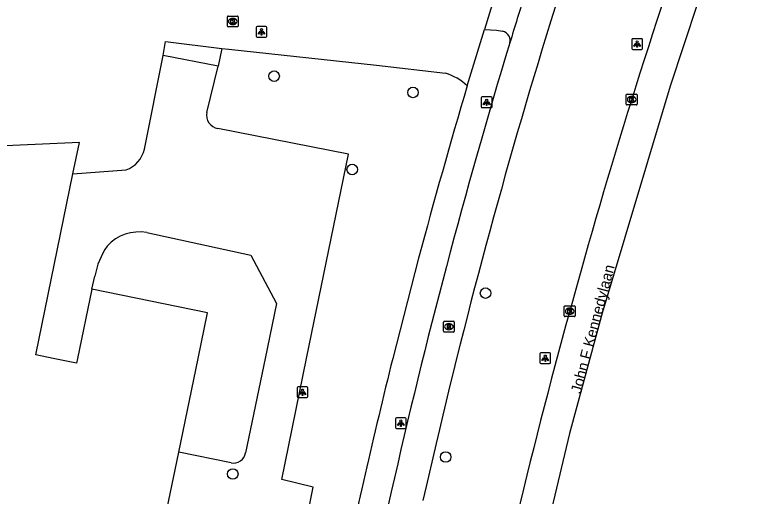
# Model space of a CAD drawing. Extents: x 161243 to 161752, y 384138 to 384885.
# Drawn here: x 161438.2 to 161506.3, y 384237.2 to 384281.9 of the extents above; entities that cross this region are included whole.
import ezdxf

# ---------------------------------------------------------------- set-up
doc = ezdxf.new("R2010")
doc.units = 0
for name, color, linetype in [('IMGEO_Boom', 7, 'Continuous'), ('IMGEO_Fietspad_gesloten', 7, 'Continuous'), ('IMGEO_Groenvoorziening', 7, 'Continuous'), ('IMGEO_Kolk', 7, 'Continuous'), ('IMGEO_Lichtpunt', 7, 'Continuous'), ('IMGEO_Openbare_ruimte_label', 7, 'Continuous'), ('IMGEO_Pand', 7, 'Continuous'), ('IMGEO_Rijbaan_lokaal_gesloten', 7, 'Continuous'), ('IMGEO_Rijbaan_lokaal_open', 7, 'Continuous'), ('IMGEO_Rioolput', 7, 'Continuous'), ('IMGEO_Voetpad_open', 7, 'Continuous')]:
    doc.layers.add(name, color=color, linetype=linetype)

msp = doc.modelspace()

# ---------------------------------------------------------------- linework, layer by layer
at = {"layer": 'IMGEO_Boom'}
for centre in [(161462.249, 384276.166), (161475.127, 384274.655), (161469.493, 384267.513), (161481.864, 384256.054), (161478.156, 384240.853), (161458.419, 384239.283)]:
    msp.add_circle(centre, 0.489, dxfattribs=at)
at = {"layer": 'IMGEO_Fietspad_gesloten'}
for centre, radius, start, end in [((162039.774, 384110.274), 577.749, 158.754785, 167.348346), ((162085.069, 384096.396), 628.16, 162.645157, 163.07631), ((162043.469, 384109.252), 584.62, 163.094928, 167.316644), ((162230.462, 384065.754), 776.602, 167.214855, 171.164573)]:
    msp.add_arc(centre, radius, start, end, dxfattribs=at)
at = {"layer": 'IMGEO_Groenvoorziening'}
msp.add_lwpolyline([(161457.397, 384278.741), (161458.047, 384278.662), (161471.733, 384277.186), (161478.143, 384276.429)], dxfattribs=at)
msp.add_arc((161476.684, 384271.558), 5.085, 46.92156, 73.32555, dxfattribs=at)
at = {"layer": 'IMGEO_Kolk'}
for p, q in [((161457.92, 384280.81), (161457.92, 384281.662)), ((161457.995, 384281.736), (161458.847, 384281.736)), ((161458.408, 384281.516), (161458.433, 384281.516)), ((161458.921, 384281.662), (161458.921, 384280.81)), ((161458.847, 384280.736), (161457.995, 384280.736)), ((161458.431, 384280.956), (161458.406, 384280.956)), ((161494.91, 384273.573), (161494.91, 384274.425)), ((161494.985, 384274.499), (161495.837, 384274.499)), ((161495.398, 384274.279), (161495.423, 384274.279)), ((161495.911, 384274.425), (161495.911, 384273.573)), ((161495.421, 384273.719), (161495.396, 384273.719)), ((161495.837, 384273.499), (161494.985, 384273.499)), ((161489.164, 384253.944), (161489.164, 384254.796)), ((161489.239, 384254.87), (161490.091, 384254.87)), ((161489.652, 384254.65), (161489.677, 384254.65)), ((161490.165, 384254.796), (161490.165, 384253.944)), ((161490.091, 384253.87), (161489.239, 384253.87)), ((161489.675, 384254.09), (161489.65, 384254.09))]:
    msp.add_line(p, q, dxfattribs=at)
for points in [[(161457.92, 384280.81), (161457.92, 384281.662)], [(161457.995, 384281.736), (161458.847, 384281.736)], [(161458.241, 384281.436), (161458.364, 384281.436), (161458.364, 384281.285), (161458.494, 384281.436), (161458.658, 384281.436), (161458.512, 384281.285), (161458.665, 384281.036), (161458.513, 384281.036), (161458.428, 384281.2), (161458.364, 384281.133), (161458.364, 384281.036), (161458.241, 384281.036), (161458.241, 384281.436)], [(161458.921, 384281.662), (161458.921, 384280.81)], [(161458.847, 384280.736), (161457.995, 384280.736)], [(161494.91, 384273.573), (161494.91, 384274.425)], [(161494.985, 384274.499), (161495.837, 384274.499)], [(161495.911, 384274.425), (161495.911, 384273.573)], [(161495.231, 384274.199), (161495.354, 384274.199), (161495.354, 384274.048), (161495.484, 384274.199), (161495.648, 384274.199), (161495.502, 384274.048), (161495.655, 384273.799), (161495.503, 384273.799), (161495.418, 384273.963), (161495.354, 384273.896), (161495.354, 384273.799), (161495.231, 384273.799), (161495.231, 384274.199)], [(161495.837, 384273.499), (161494.985, 384273.499)], [(161489.164, 384253.944), (161489.164, 384254.796)], [(161489.239, 384254.87), (161490.091, 384254.87)], [(161489.485, 384254.57), (161489.608, 384254.57), (161489.608, 384254.419), (161489.738, 384254.57), (161489.902, 384254.57), (161489.756, 384254.419), (161489.909, 384254.17), (161489.757, 384254.17), (161489.672, 384254.334), (161489.608, 384254.267), (161489.608, 384254.17), (161489.485, 384254.17), (161489.485, 384254.57)], [(161490.165, 384254.796), (161490.165, 384253.944)], [(161490.091, 384253.87), (161489.239, 384253.87)]]:
    msp.add_lwpolyline(points, dxfattribs=at)
for centre, start, end in [((161457.997, 384281.66), 91.55205, 178.44795), ((161457.997, 384281.66), 91.55205, 178.44795), ((161458.845, 384281.66), 1.55205, 88.44795), ((161458.845, 384281.66), 1.55205, 88.44795), ((161457.997, 384280.812), 181.55205, 268.44795), ((161457.997, 384280.812), 181.55205, 268.44795), ((161458.845, 384280.812), 271.55205, 358.44795), ((161458.845, 384280.812), 271.55205, 358.44795), ((161494.987, 384274.423), 91.55205, 178.44795), ((161494.987, 384274.423), 91.55205, 178.44795), ((161495.835, 384274.423), 1.55205, 88.44795), ((161495.835, 384274.423), 1.55205, 88.44795), ((161494.987, 384273.575), 181.55205, 268.44795), ((161494.987, 384273.575), 181.55205, 268.44795), ((161495.835, 384273.575), 271.55205, 358.44795), ((161495.835, 384273.575), 271.55205, 358.44795), ((161489.241, 384254.794), 91.55205, 178.44795), ((161489.241, 384254.794), 91.55205, 178.44795), ((161490.089, 384254.794), 1.55205, 88.44795), ((161490.089, 384254.794), 1.55205, 88.44795), ((161489.241, 384253.946), 181.55205, 268.44795), ((161489.241, 384253.946), 181.55205, 268.44795), ((161490.089, 384253.946), 271.55205, 358.44795), ((161490.089, 384253.946), 271.55205, 358.44795)]:
    msp.add_arc(centre, 0.0765, start, end, dxfattribs=at)
for centre, major_axis, ratio, start_param, end_param in [((161458.407, 384281.236), (-0.387, 0.002), 0.722429, 4.712389, 7.853982), ((161458.432, 384281.236), (-0.39, 0.002), 0.717154, 1.570796, 4.712389), ((161495.397, 384273.999), (-0.387, 0.002), 0.722429, 4.712389, 7.853982), ((161495.422, 384273.999), (-0.39, 0.002), 0.717154, 1.570796, 4.712389), ((161489.651, 384254.37), (-0.387, 0.002), 0.722429, 4.712389, 7.853982), ((161489.676, 384254.37), (-0.39, 0.002), 0.717154, 1.570796, 4.712389)]:
    msp.add_ellipse(centre, major_axis=major_axis, ratio=ratio, start_param=start_param, end_param=end_param, dxfattribs=at)
at = {"layer": 'IMGEO_Lichtpunt'}
for p, q in [((161460.583, 384280.685), (161460.583, 384279.878)), ((161460.583, 384280.685), (161460.583, 384279.878)), ((161461.485, 384280.78), (161460.677, 384280.78)), ((161461.485, 384280.78), (161460.677, 384280.78)), ((161461.579, 384279.878), (161461.579, 384280.685)), ((161461.579, 384279.878), (161461.579, 384280.685)), ((161460.677, 384279.784), (161461.485, 384279.784)), ((161460.677, 384279.784), (161461.485, 384279.784)), ((161495.414, 384279.545), (161495.414, 384278.738)), ((161495.414, 384279.545), (161495.414, 384278.738)), ((161496.316, 384279.64), (161495.508, 384279.64)), ((161496.316, 384279.64), (161495.508, 384279.64)), ((161496.41, 384278.738), (161496.41, 384279.545)), ((161496.41, 384278.738), (161496.41, 384279.545)), ((161495.508, 384278.644), (161496.316, 384278.644)), ((161495.508, 384278.644), (161496.316, 384278.644)), ((161481.464, 384274.145), (161481.464, 384273.338)), ((161481.464, 384274.145), (161481.464, 384273.338)), ((161482.366, 384274.24), (161481.558, 384274.24)), ((161482.366, 384274.24), (161481.558, 384274.24)), ((161482.46, 384273.338), (161482.46, 384274.145)), ((161482.46, 384273.338), (161482.46, 384274.145)), ((161481.558, 384273.244), (161482.366, 384273.244)), ((161481.558, 384273.244), (161482.366, 384273.244)), ((161486.901, 384250.415), (161486.901, 384249.608)), ((161486.901, 384250.415), (161486.901, 384249.608)), ((161487.803, 384250.51), (161486.995, 384250.51)), ((161487.803, 384250.51), (161486.995, 384250.51)), ((161487.897, 384249.608), (161487.897, 384250.415)), ((161487.897, 384249.608), (161487.897, 384250.415)), ((161486.995, 384249.514), (161487.803, 384249.514)), ((161486.995, 384249.514), (161487.803, 384249.514)), ((161464.383, 384247.263), (161464.383, 384246.456)), ((161464.383, 384247.263), (161464.383, 384246.456)), ((161465.285, 384247.358), (161464.477, 384247.358)), ((161465.285, 384247.358), (161464.477, 384247.358)), ((161465.379, 384246.456), (161465.379, 384247.263)), ((161465.379, 384246.456), (161465.379, 384247.263)), ((161464.477, 384246.362), (161465.285, 384246.362)), ((161464.477, 384246.362), (161465.285, 384246.362)), ((161473.5, 384244.399), (161473.5, 384243.592)), ((161473.5, 384244.399), (161473.5, 384243.592)), ((161474.402, 384244.494), (161473.594, 384244.494)), ((161474.402, 384244.494), (161473.594, 384244.494)), ((161474.496, 384243.592), (161474.496, 384244.399)), ((161474.496, 384243.592), (161474.496, 384244.399)), ((161473.594, 384243.498), (161474.402, 384243.498)), ((161473.594, 384243.498), (161474.402, 384243.498))]:
    msp.add_line(p, q, dxfattribs=at)
for points in [[(161460.957, 384280.349), (161460.996, 384280.321), (161460.808, 384280.059), (161460.77, 384280.086), (161460.957, 384280.349)], [(161461.059, 384280.301), (161461.106, 384280.301), (161461.106, 384279.979), (161461.059, 384279.979), (161461.059, 384280.301)], [(161461.169, 384280.321), (161461.207, 384280.348), (161461.394, 384280.086), (161461.355, 384280.058), (161461.169, 384280.321)], [(161495.788, 384279.209), (161495.827, 384279.181), (161495.639, 384278.919), (161495.601, 384278.946), (161495.788, 384279.209)], [(161495.89, 384279.161), (161495.937, 384279.161), (161495.937, 384278.839), (161495.89, 384278.839), (161495.89, 384279.161)], [(161496, 384279.181), (161496.038, 384279.208), (161496.225, 384278.946), (161496.186, 384278.918), (161496, 384279.181)], [(161481.838, 384273.809), (161481.877, 384273.781), (161481.689, 384273.519), (161481.651, 384273.546), (161481.838, 384273.809)], [(161481.94, 384273.761), (161481.987, 384273.761), (161481.987, 384273.439), (161481.94, 384273.439), (161481.94, 384273.761)], [(161482.05, 384273.781), (161482.088, 384273.808), (161482.275, 384273.546), (161482.236, 384273.518), (161482.05, 384273.781)], [(161487.275, 384250.079), (161487.314, 384250.051), (161487.126, 384249.789), (161487.088, 384249.816), (161487.275, 384250.079)], [(161487.377, 384250.031), (161487.424, 384250.031), (161487.424, 384249.709), (161487.377, 384249.709), (161487.377, 384250.031)], [(161487.487, 384250.051), (161487.525, 384250.078), (161487.712, 384249.816), (161487.673, 384249.788), (161487.487, 384250.051)], [(161464.757, 384246.927), (161464.796, 384246.899), (161464.608, 384246.637), (161464.57, 384246.664), (161464.757, 384246.927)], [(161464.859, 384246.879), (161464.906, 384246.879), (161464.906, 384246.557), (161464.859, 384246.557), (161464.859, 384246.879)], [(161464.969, 384246.899), (161465.007, 384246.926), (161465.194, 384246.664), (161465.155, 384246.636), (161464.969, 384246.899)], [(161473.874, 384244.063), (161473.913, 384244.035), (161473.725, 384243.773), (161473.687, 384243.8), (161473.874, 384244.063)], [(161473.976, 384244.015), (161474.023, 384244.015), (161474.023, 384243.693), (161473.976, 384243.693), (161473.976, 384244.015)], [(161474.086, 384244.035), (161474.124, 384244.062), (161474.311, 384243.8), (161474.272, 384243.772), (161474.086, 384244.035)]]:
    msp.add_lwpolyline(points, dxfattribs=at)
for centre in [(161461.082, 384280.483), (161495.913, 384279.343), (161481.963, 384273.943), (161487.4, 384250.213), (161464.882, 384247.061), (161473.999, 384244.197)]:
    msp.add_circle(centre, 0.0994, dxfattribs=at)
for centre, start, end in [((161460.677, 384280.685), 90, 180), ((161460.677, 384280.685), 90, 180), ((161461.485, 384280.685), 0, 90), ((161461.485, 384280.685), 0, 90), ((161460.677, 384279.878), 180, 270), ((161460.677, 384279.878), 180, 270), ((161461.485, 384279.878), 270, 0), ((161461.485, 384279.878), 270, 360), ((161495.508, 384279.545), 90, 180), ((161495.508, 384279.545), 90, 180), ((161496.316, 384279.545), 0, 90), ((161496.316, 384279.545), 0, 90), ((161495.508, 384278.738), 180, 270), ((161495.508, 384278.738), 180, 270), ((161496.316, 384278.738), 270, 0), ((161496.316, 384278.738), 270, 360), ((161481.558, 384274.145), 90, 180), ((161481.558, 384274.145), 90, 180), ((161482.366, 384274.145), 0, 90), ((161482.366, 384274.145), 0, 90), ((161481.558, 384273.338), 180, 270), ((161481.558, 384273.338), 180, 270), ((161482.366, 384273.338), 270, 0), ((161482.366, 384273.338), 270, 360), ((161486.995, 384250.415), 90, 180), ((161486.995, 384250.415), 90, 180), ((161487.803, 384250.415), 0, 90), ((161487.803, 384250.415), 0, 90), ((161486.995, 384249.608), 180, 270), ((161486.995, 384249.608), 180, 270), ((161487.803, 384249.608), 270, 0), ((161487.803, 384249.608), 270, 360), ((161464.477, 384247.263), 90, 180), ((161464.477, 384247.263), 90, 180), ((161465.285, 384247.263), 0, 90), ((161465.285, 384247.263), 0, 90), ((161464.477, 384246.456), 180, 270), ((161464.477, 384246.456), 180, 270), ((161465.285, 384246.456), 270, 0), ((161465.285, 384246.456), 270, 360), ((161473.594, 384244.399), 90, 180), ((161473.594, 384244.399), 90, 180), ((161474.402, 384244.399), 0, 90), ((161474.402, 384244.399), 0, 90), ((161473.594, 384243.592), 180, 270), ((161473.594, 384243.592), 180, 270), ((161474.402, 384243.592), 270, 0), ((161474.402, 384243.592), 270, 360)]:
    msp.add_arc(centre, 0.0946, start, end, dxfattribs=at)
at = {"layer": 'IMGEO_Pand'}
for points in [[(161443.595, 384267.101), (161444.19, 384270.006), (161409.789, 384268.472)], [(161445.345, 384256.428), (161444.012, 384250), (161443.92, 384249.556), (161441.755, 384250), (161440.16, 384250.327), (161443.595, 384267.101)], [(161453.42, 384241.315), (161455.21, 384250), (161456.081, 384254.229), (161445.345, 384256.428)], [(161452.162, 384235.232), (161453.42, 384241.315)]]:
    msp.add_lwpolyline(points, dxfattribs=at)
at = {"layer": 'IMGEO_Rijbaan_lokaal_gesloten'}
msp.add_lwpolyline([(161638.668, 384567.921), (161627.681, 384546.777), (161605.302, 384502.824), (161593.763, 384479.586), (161574.873, 384442.021), (161545.035, 384383.956), (161539.238, 384372.041), (161525.285, 384343.063), (161517.236, 384325.784), (161510.904, 384308.827), (161504.035, 384290.582), (161498.991, 384275.235), (161492.66, 384254.201), (161489.655, 384243.039), (161484.933, 384223.293), (161481.713, 384206.981), (161478.494, 384189.488), (161475.768, 384168.523)], dxfattribs=at)
for centre, radius, start, end in [((162042.579, 384103.171), 573.215, 160.615638, 164.705887), ((162060.147, 384097.056), 591.775, 164.583524, 168.642877)]:
    msp.add_arc(centre, radius, start, end, dxfattribs=at)
at = {"layer": 'IMGEO_Rijbaan_lokaal_open'}
for points in [[(161451.978, 384278.094), (161452.194, 384279.379), (161457.397, 384278.741)], [(161457.397, 384278.741), (161457.055, 384277.085)], [(161450.22, 384269.4), (161451.978, 384278.094)], [(161457.055, 384277.085), (161451.978, 384278.094)], [(161456.002, 384272.782), (161457.055, 384277.085)], [(161464.156, 384229.33), (161465.863, 384238.046), (161462.953, 384238.76), (161465.264, 384250), (161469.159, 384268.947), (161457.031, 384271.325)], [(161443.595, 384267.101), (161448.521, 384267.466)], [(161450.444, 384261.666), (161460.096, 384259.576), (161462.459, 384255.089), (161461.408, 384250), (161459.6, 384241.243)], [(161445.345, 384256.428), (161445.632, 384257.63)], [(161458.265, 384240.323), (161453.42, 384241.315)]]:
    msp.add_lwpolyline(points, dxfattribs=at)
for centre, radius, start, end in [((161457.21, 384272.543), 1.231, 168.80897, 261.654), ((161447.603, 384269.985), 2.681, 290.01163, 347.39039), ((161449.752, 384257.693), 4.033, 80.12473, 137.60477), ((161452.571, 384256.407), 7.046, 145.36033, 170.00376), ((161458.499, 384241.412), 1.114, 257.89373, 351.25072)]:
    msp.add_arc(centre, radius, start, end, dxfattribs=at)
at = {"layer": 'IMGEO_Rioolput'}
for p, q in [((161477.957, 384252.514), (161477.957, 384253.366)), ((161478.032, 384253.44), (161478.884, 384253.44)), ((161478.445, 384253.22), (161478.47, 384253.22)), ((161478.958, 384253.366), (161478.958, 384252.514)), ((161478.468, 384252.66), (161478.443, 384252.66)), ((161478.884, 384252.44), (161478.032, 384252.44))]:
    msp.add_line(p, q, dxfattribs=at)
for points in [[(161477.957, 384252.514), (161477.957, 384253.366)], [(161478.032, 384253.44), (161478.884, 384253.44)], [(161478.546, 384253.138), (161478.294, 384253.14), (161478.294, 384252.74)], [(161478.958, 384253.366), (161478.958, 384252.514)], [(161478.294, 384252.74), (161478.418, 384252.74), (161478.418, 384252.902), (161478.429, 384252.902)], [(161478.472, 384253.059), (161478.418, 384253.059), (161478.418, 384252.978)], [(161478.418, 384252.978), (161478.47, 384252.978)], [(161478.476, 384252.873), (161478.547, 384252.74), (161478.687, 384252.74), (161478.622, 384252.866)], [(161478.884, 384252.44), (161478.032, 384252.44)]]:
    msp.add_lwpolyline(points, dxfattribs=at)
for centre, radius, start, end in [((161478.034, 384253.364), 0.0765, 91.55205, 178.44795), ((161478.034, 384253.364), 0.0765, 91.55205, 178.44795), ((161478.545, 384253.028), 0.109, 350.36119, 89.41601), ((161478.882, 384253.364), 0.0765, 1.55205, 88.44795), ((161478.882, 384253.364), 0.0765, 1.55205, 88.44795), ((161478.034, 384252.516), 0.0765, 181.55205, 268.44795), ((161478.034, 384252.516), 0.0765, 181.55205, 268.44795), ((161478.428, 384252.849), 0.0533, 26.02933, 88.69889), ((161478.454, 384253.167), 0.19, 274.7715, 282.96867), ((161478.478, 384252.963), 0.0964, 77.00612, 93.18647), ((161478.492, 384253.02), 0.0378, 276.66336, 79.67722), ((161478.543, 384253.028), 0.112, 277.58423, 350.98172), ((161478.527, 384252.813), 0.108, 29.51342, 73.79051), ((161478.882, 384252.516), 0.0765, 271.55205, 358.44795), ((161478.882, 384252.516), 0.0765, 271.55205, 358.44795)]:
    msp.add_arc(centre, radius, start, end, dxfattribs=at)
for centre, major_axis, ratio, start_param, end_param in [((161478.444, 384252.94), (-0.387, 0.002), 0.722429, 4.712389, 7.853982), ((161478.469, 384252.94), (-0.39, 0.002), 0.717154, 1.570796, 4.712389)]:
    msp.add_ellipse(centre, major_axis=major_axis, ratio=ratio, start_param=start_param, end_param=end_param, dxfattribs=at)
at = {"layer": 'IMGEO_Voetpad_open'}
for points in [[(161482.704, 384283.536), (161481.761, 384280.475)], [(161480.157, 384275.272), (161481.761, 384280.475)], [(161481.761, 384280.475), (161482.86, 384280.419), (161483.417, 384280.333)], [(161475.649, 384259.281), (161473.257, 384250)]]:
    msp.add_lwpolyline(points, dxfattribs=at)
for centre, radius, start, end in [((161483.249, 384279.46), 0.889, 26.89796, 79.09868), ((161483.248, 384279.462), 0.889, 346.33867, 26.75391), ((162093.062, 384093.858), 639.189, 163.511743, 165.001059), ((162044.09, 384107.797), 588.279, 166.011457, 168.161921)]:
    msp.add_arc(centre, radius, start, end, dxfattribs=at)

# ---------------------------------------------------------------- texts
at = {"layer": 'IMGEO_Openbare_ruimte_label'}
msp.add_text('John F Kennedylaan', height=1, rotation=75.17189, dxfattribs=at).set_placement((161490.713, 384246.678))

doc.saveas('drawing.dxf')
